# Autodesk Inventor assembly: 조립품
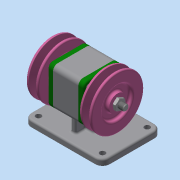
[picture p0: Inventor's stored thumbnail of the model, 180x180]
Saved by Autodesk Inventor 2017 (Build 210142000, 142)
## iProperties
Part Number: 조립품
Material: 일반
Document SubType Name: Assembly
Designer: mrc
Author: mrc
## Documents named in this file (10)
- C:\Users\mrc\Desktop\701106V1015\조립품.iam
- C:\Users\mrc\Desktop\701106V1015\V-벨트풀리.ipt
- C:\Users\mrc\Desktop\701106V1015\너트 M10x1.ipt
- C:\Users\mrc\Desktop\701106V1015\베어링 6004.ipt
- C:\Users\mrc\Desktop\701106V1015\본체.ipt
- C:\Users\mrc\Desktop\701106V1015\볼트 M4.ipt
- C:\Users\mrc\Desktop\701106V1015\오일 실 17 30 5.ipt
- C:\Users\mrc\Desktop\701106V1015\축.ipt
- C:\Users\mrc\Desktop\701106V1015\커버.ipt
- C:\Users\mrc\Desktop\701106V1015\키 5 x 5 x 12.ipt
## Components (2 placed, 1 different names)
1. V-벨트풀리:2
2. V-벨트풀리:3
